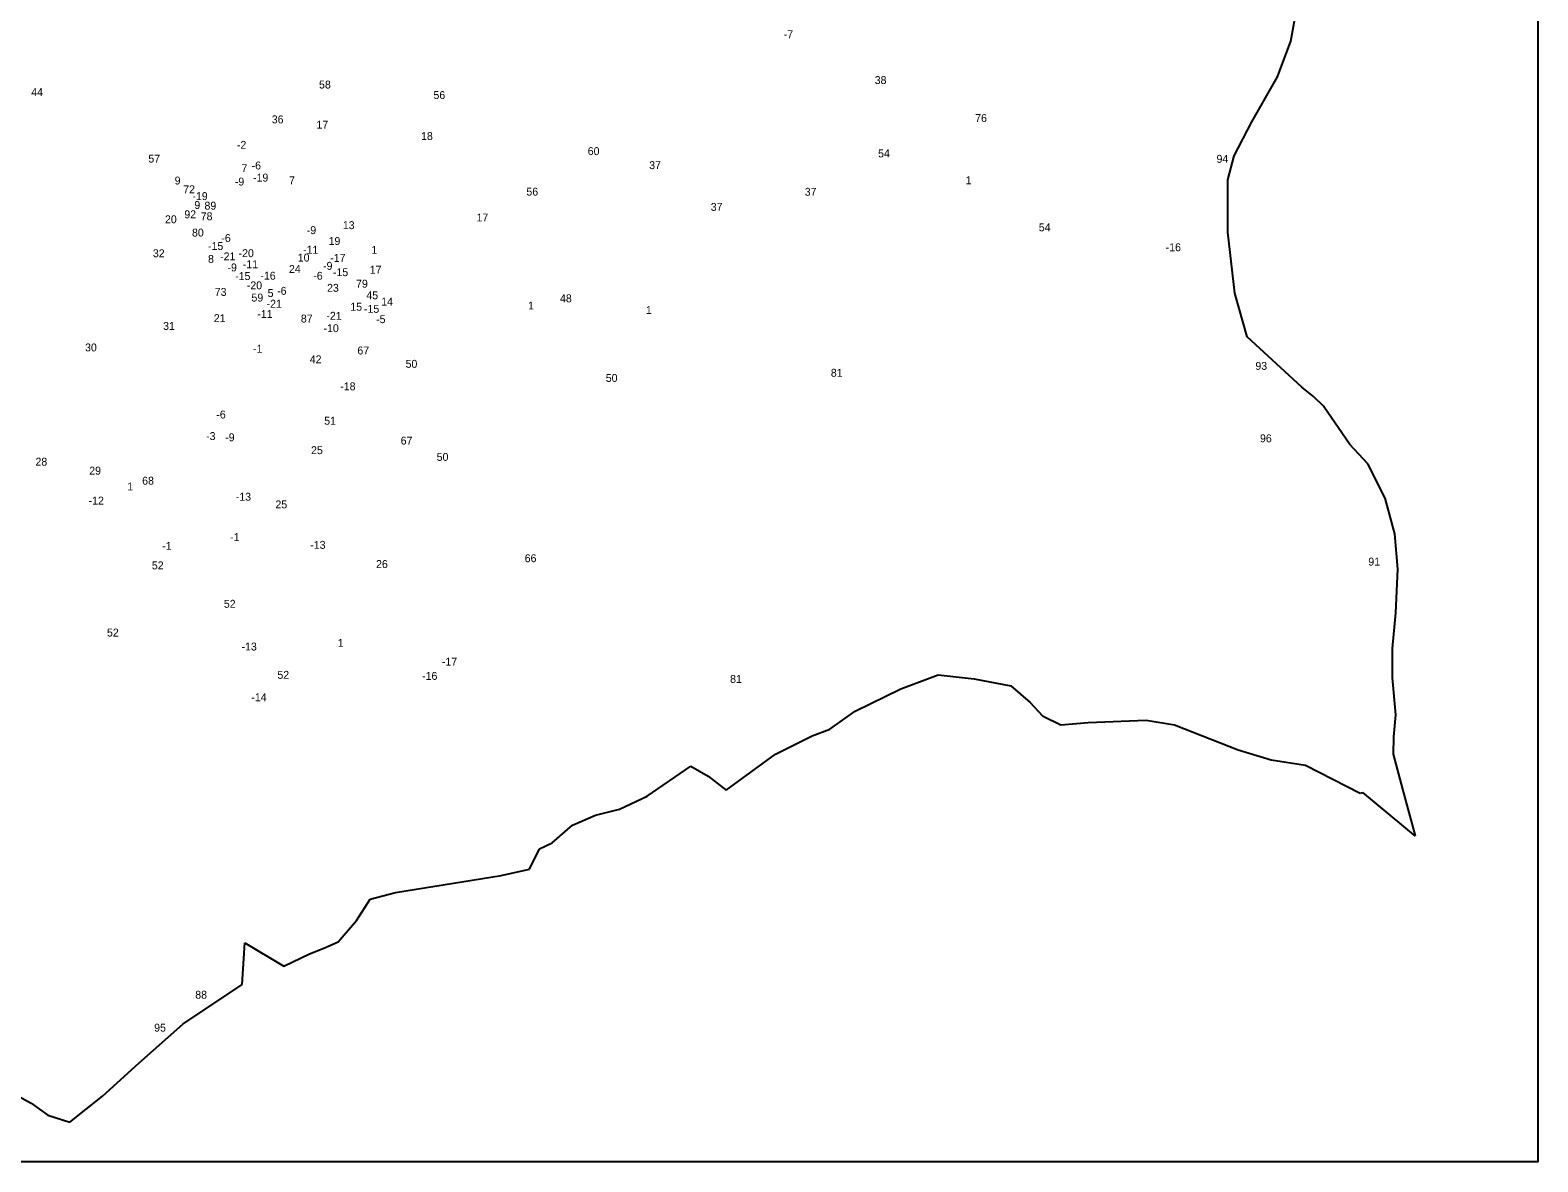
# Model space of a CAD drawing. Extents: x -772884 to -769704, y -986653 to -984166.
# Drawn here: x -771287 to -769704, y -986653 to -985466 of the extents above; entities that cross this region are included whole.
import ezdxf

# ---------------------------------------------------------------- set-up
doc = ezdxf.new("R2010")
doc.units = 0
doc.layers.add('Vrstva 15', color=7, linetype='Continuous')
doc.layers.add('Vrstva 24', color=7, linetype='Continuous')

msp = doc.modelspace()

# ---------------------------------------------------------------- linework, layer by layer
at = {"layer": 'Vrstva 15'}
for p, q in [((-769963.68, -985477.01), (-769959.57, -985453.88)), ((-769977.56, -985514.57), (-769963.68, -985477.01)), ((-770004.65, -985561.61), (-769977.56, -985514.57)), ((-770023.14, -985597.46), (-770004.65, -985561.61)), ((-770029.9, -985622.57), (-770023.14, -985597.46)), ((-770029.68, -985677.32), (-770029.9, -985622.57)), ((-770022.57, -985741.4), (-770029.68, -985677.32)), ((-770009.58, -985787.31), (-770022.57, -985741.4)), ((-769952.24, -985840.18), (-770009.58, -985787.31)), ((-769939.98, -985850.02), (-769952.24, -985840.18)), ((-769929.56, -985860.04), (-769939.98, -985850.02)), ((-769901.67, -985900.13), (-769929.56, -985860.04)), ((-769883.01, -985920.7), (-769901.67, -985900.13)), ((-769864.73, -985956.65), (-769883.01, -985920.7)), ((-769854.39, -985994.11), (-769864.73, -985956.65)), ((-769851.45, -986030.98), (-769854.39, -985994.11)), ((-769853.66, -986077.1), (-769851.45, -986030.98)), ((-769856.82, -986114.33), (-769853.66, -986077.1)), ((-769856.89, -986144.99), (-769856.82, -986114.33)), ((-770373.08, -986156.66), (-770333.81, -986142.16)), ((-770333.81, -986142.16), (-770296, -986146.09)), ((-769853.37, -986183.91), (-769856.89, -986144.99)), ((-770420.94, -986180.16), (-770373.08, -986156.66)), ((-770296, -986146.09), (-770257.54, -986153.43)), ((-770257.54, -986153.43), (-770237.35, -986170.86)), ((-770237.35, -986170.86), (-770224.36, -986184.89)), ((-770447.37, -986198.96), (-770420.94, -986180.16)), ((-770224.36, -986184.89), (-770205.2, -986194.58)), ((-770205.2, -986194.58), (-770176.21, -986191.94)), ((-770176.21, -986191.94), (-770115.57, -986189.55)), ((-770115.57, -986189.55), (-770085.62, -986194.55)), ((-769855.72, -986207.11), (-769853.37, -986183.91)), ((-770504.33, -986225.4), (-770466.16, -986206.01)), ((-770466.16, -986206.01), (-770447.37, -986198.96)), ((-770085.62, -986194.55), (-770018.82, -986220.69)), ((-769855.86, -986225.18), (-769855.72, -986207.11)), ((-770018.82, -986220.69), (-769984.47, -986231.26)), ((-770639.11, -986269.27), (-770593.38, -986237.8)), ((-770593.38, -986237.8), (-770575.03, -986248.49)), ((-770556.32, -986263.1), (-770504.33, -986225.4)), ((-769984.47, -986231.26), (-769948.35, -986236.85)), ((-769948.35, -986236.85), (-769890.96, -986266.04)), ((-769846.17, -986262.04), (-769855.86, -986225.18)), ((-770575.03, -986248.49), (-770556.32, -986263.1)), ((-770668.17, -986282.86), (-770639.11, -986269.27)), ((-769891.005, -986266.129), (-769888.46, -986265.6)), ((-769888.46, -986265.6), (-769833.18, -986311.41)), ((-769832.861, -986311.025), (-769846.17, -986262.04)), ((-770693.42, -986289.1), (-770668.17, -986282.86)), ((-770738.7, -986318.25), (-770717.49, -986299.6)), ((-770717.49, -986299.6), (-770693.42, -986289.1)), ((-770752.14, -986324.6), (-770738.7, -986318.25)), ((-770762.56, -986346.04), (-770752.14, -986324.6)), ((-770792.21, -986352.48), (-770762.56, -986346.04)), ((-770903.4, -986370.53), (-770792.21, -986352.48)), ((-770944.02, -986399.63), (-770929.84, -986377.28)), ((-770929.84, -986377.28), (-770903.4, -986370.53)), ((-770963.32, -986422.08), (-770944.02, -986399.63)), ((-771064.01, -986467.12), (-771061.37, -986423.08)), ((-771061.37, -986423.08), (-771020.57, -986447.74)), ((-770993.56, -986434.82), (-770978.51, -986428.69)), ((-770978.51, -986428.69), (-770963.32, -986422.08)), ((-771020.57, -986447.74), (-770993.56, -986434.82)), ((-771126.54, -986508.53), (-771064.01, -986467.12)), ((-771172.48, -986549.35), (-771126.54, -986508.53)), ((-771210.64, -986584), (-771172.48, -986549.35)), ((-771312.95, -986576.54), (-771285.5, -986591.52)), ((-771244.99, -986611.47), (-771210.64, -986584)), ((-771285.5, -986591.52), (-771268.03, -986604.2)), ((-771268.03, -986604.2), (-771244.99, -986611.47))]:
    msp.add_line(p, q, dxfattribs=at)
msp.add_lwpolyline([(-772883.58, -984166.02), (-769704.46, -984166.02), (-769704.46, -986653.05), (-772883.58, -986653.05)], close=True, dxfattribs=at)

# ---------------------------------------------------------------- texts
at = {"layer": 'Vrstva 24'}
for s, height, p in [('-7', 8.2944, (-770495.854, -985473.945)), ('44', 8.2944, (-771285.494, -985534.665)), ('58', 8.2944, (-770983.483, -985526.715)), ('38', 8.2944, (-770400.353, -985522.055)), ('56', 8.2944, (-770863.417, -985537.785)), ('36', 8.2944, (-771033.077, -985563.315)), ('76', 8.2944, (-770294.939, -985561.935)), ('17', 8.2944, (-770986.179, -985568.865)), ('18', 8.2944, (-770876.406, -985580.765)), ('-2', 8.2944, (-771069.701, -985590.005)), ('60', 8.2944, (-770701.494, -985596.585)), ('54', 8.2944, (-770396.829, -985598.975)), ('57', 8.2944, (-771162.616, -985604.465)), ('7', 8.294, (-771064.888, -985614.475)), ('-6', 8.2944, (-771054.275, -985611.685)), ('37', 8.2944, (-770637.056, -985611.315)), ('94', 8.2944, (-770041.642, -985604.695)), ('9', 8.294, (-771135.01, -985627.425)), ('-9', 8.2944, (-771071.885, -985628.545)), ('-19', 8.2944, (-771052.736, -985624.385)), ('7', 8.294, (-771014.938, -985627.175)), ('1', 8.294, (-770304.92, -985627.175)), ('72', 8.2944, (-771126.025, -985636.665)), ('-19', 8.2944, (-771116.386, -985643.795)), ('56', 8.2944, (-770765.867, -985639.095)), ('37', 8.2944, (-770473.776, -985639.265)), ('92', 8.2944, (-771124.856, -985662.925)), ('9', 8.294, (-771114.35, -985653.165)), ('89', 8.2944, (-771103.687, -985653.855)), ('37', 8.2944, (-770572.416, -985655.095)), ('20', 8.2944, (-771145.17, -985668.135)), ('78', 8.2944, (-771107.645, -985664.955)), ('13', 8.2944, (-770958.506, -985674.255)), ('17', 8.2944, (-770818.189, -985666.195)), ('54', 8.2944, (-770228.149, -985676.565)), ('80', 8.2944, (-771116.81, -985682.065)), ('-6', 8.2944, (-771086.015, -985687.805)), ('-9', 8.2944, (-770996.375, -985679.525)), ('19', 8.2944, (-770973.461, -985690.925)), ('32', 8.2944, (-771157.843, -985703.755)), ('-15', 8.2944, (-771100.002, -985696.215)), ('8', 8.294, (-771099.986, -985709.735)), ('-21', 8.2944, (-771087.312, -985707.055)), ('-20', 8.2944, (-771067.906, -985703.665)), ('10', 8.2944, (-771005.804, -985708.305)), ('-11', 8.2944, (-771000.256, -985700.105)), ('-17', 8.2944, (-770971.744, -985708.645)), ('1', 8.294, (-770928.48, -985700.215)), ('-16', 8.2944, (-770095.036, -985697.505)), ('-9', 8.2944, (-771079.585, -985718.645)), ('-11', 8.2944, (-771063.516, -985715.275)), ('24', 8.2944, (-771015.059, -985720.255)), ('-9', 8.2944, (-770979.275, -985716.945)), ('-15', 8.2944, (-770968.872, -985723.635)), ('17', 8.2944, (-770930.289, -985721.095)), ('-15', 8.2944, (-771071.552, -985727.715)), ('-20', 8.2944, (-771059.286, -985737.435)), ('-16', 8.2944, (-771045.036, -985727.335)), ('-6', 8.2944, (-770989.525, -985727.355)), ('23', 8.2944, (-770975.053, -985740.045)), ('79', 8.2944, (-770944.639, -985735.685)), ('73', 8.2944, (-771092.925, -985744.335)), ('59', 8.2944, (-771054.417, -985750.265)), ('-21', 8.2944, (-771038.552, -985756.755)), ('5', 8.294, (-771037.426, -985745.475)), ('-6', 8.2944, (-771027.445, -985743.185)), ('45', 8.2944, (-770933.818, -985747.875)), ('14', 8.2944, (-770918.242, -985754.535)), ('48', 8.2944, (-770730.628, -985751.085)), ('21', 8.2944, (-771093.916, -985771.875)), ('-11', 8.2944, (-771048.256, -985767.485)), ('87', 8.2944, (-771002.566, -985772.295)), ('-21', 8.2944, (-770975.752, -985769.385)), ('15', 8.2944, (-770950.706, -985759.925)), ('-15', 8.2944, (-770936.322, -985762.095)), ('-5', 8.2944, (-770923.581, -985772.935)), ('1', 8.294, (-770764.07, -985758.605)), ('1', 8.294, (-770640.48, -985763.345)), ('31', 8.2944, (-771147.126, -985780.045)), ('-10', 8.2944, (-770978.789, -985782.385)), ('30', 8.2944, (-771229.01, -985802.605)), ('-1', 8.2944, (-771052.795, -985803.995)), ('42', 8.2944, (-770993.238, -985815.075)), ('67', 8.2944, (-770943.219, -985805.815)), ('50', 8.2944, (-770892.68, -985819.795)), ('50', 8.2944, (-770682.58, -985834.615)), ('81', 8.2944, (-770446.396, -985829.195)), ('93', 8.2944, (-770000.906, -985821.965)), ('-18', 8.2944, (-770961.222, -985843.365)), ('-6', 8.2944, (-771091.295, -985872.995)), ('51', 8.2944, (-770978.056, -985879.545)), ('-3', 8.2944, (-771101.991, -985895.605)), ('-9', 8.2944, (-771081.985, -985896.875)), ('67', 8.2944, (-770897.829, -985900.365)), ('96', 8.2944, (-769996.04, -985897.975)), ('25', 8.2944, (-770991.873, -985910.375)), ('28', 8.2944, (-771281.073, -985922.485)), ('29', 8.2944, (-771224.657, -985931.915)), ('50', 8.2944, (-770860.02, -985917.475)), ('68', 8.2944, (-771169.096, -985942.425)), ('-12', 8.2944, (-771225.292, -985963.345)), ('1', 8.294, (-771184.79, -985948.465)), ('-13', 8.2944, (-771070.892, -985959.285)), ('25', 8.2944, (-771029.243, -985967.285)), ('-1', 8.2944, (-771148.035, -986010.765)), ('-1', 8.2944, (-771076.865, -986001.615)), ('-13', 8.2944, (-770992.682, -986009.755)), ('66', 8.2944, (-770767.66, -986023.805)), ('52', 8.2944, (-771158.933, -986031.295)), ('26', 8.2944, (-770923.677, -986029.935)), ('91', 8.2944, (-769882.37, -986027.395)), ('52', 8.2944, (-771083.393, -986071.615)), ('52', 8.2944, (-771206.003, -986101.775)), ('-13', 8.2944, (-771064.802, -986116.455)), ('1', 8.294, (-770963.84, -986112.585)), ('-17', 8.2944, (-770854.574, -986132.375)), ('52', 8.2944, (-771027.173, -986146.155)), ('-16', 8.2944, (-770875.336, -986147.285)), ('81', 8.2944, (-770552.096, -986150.465)), ('-14', 8.2944, (-771054.508, -986169.635)), ('88', 8.2944, (-771113.393, -986481.855)), ('95', 8.2944, (-771156.506, -986516.395))]:
    msp.add_text(s, height=height, dxfattribs=at).set_placement(p)

doc.saveas('drawing.dxf')
